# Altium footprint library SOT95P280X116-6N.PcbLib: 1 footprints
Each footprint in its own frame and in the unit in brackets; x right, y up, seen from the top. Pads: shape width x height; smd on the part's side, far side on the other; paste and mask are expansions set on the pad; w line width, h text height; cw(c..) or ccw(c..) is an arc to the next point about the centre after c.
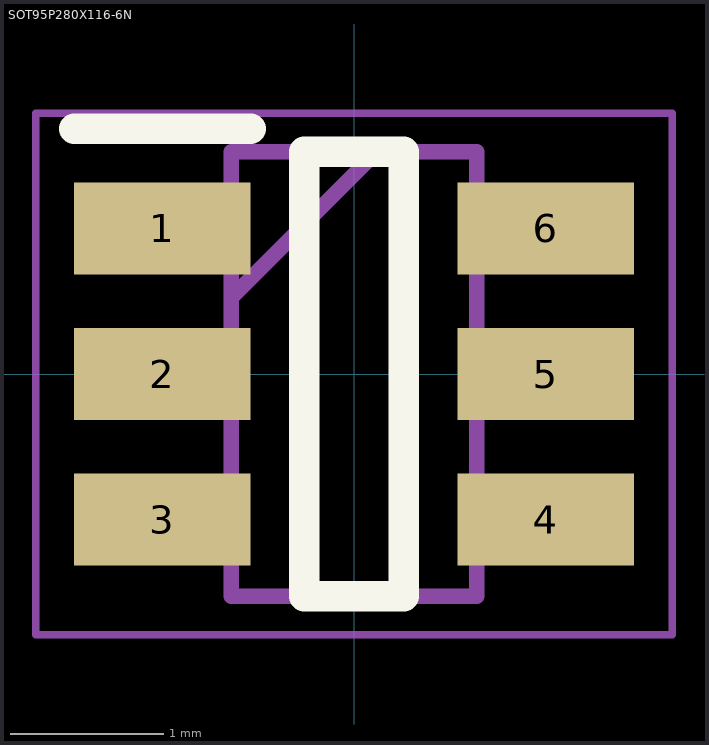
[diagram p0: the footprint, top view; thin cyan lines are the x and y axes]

## SOT95P280X116-6N [mm]
pads (6):
  rect 1.15x0.6 smd: 1(-1.25,0.95) 2(-1.25,0) 3(-1.25,-0.95) 4(1.25,-0.95) 5(1.25,0) 6(1.25,0.95)
Top Overlay:
  lines w0.2: -1.825,1.6 -0.675,1.6 ; -0.325,-1.45 0.325,-1.45 0.325,1.45 -0.325,1.45 -0.325,-1.45
Mechanical 15:
  lines w0.1: -0.8,0.5 0.15,1.45 ; -0.8,-1.45 0.8,-1.45 0.8,1.45 -0.8,1.45 -0.8,-1.45
Mechanical 20:
  lines w0.05: -2.075,-1.7 2.075,-1.7 2.075,1.7 -2.075,1.7 -2.075,-1.7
